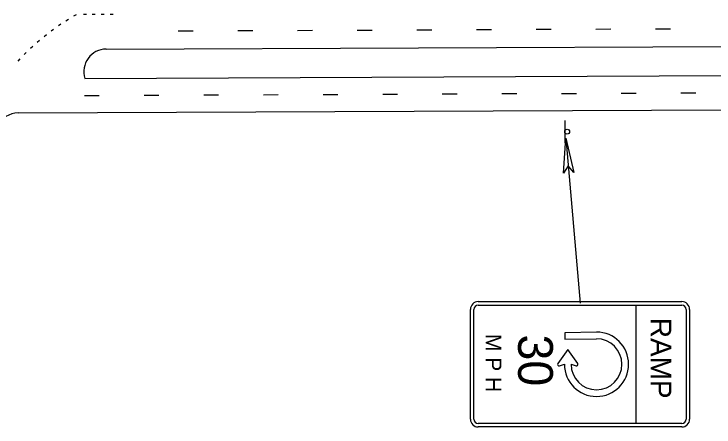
# Model space of a CAD drawing. Extents: x 582908 to 586039, y 1530940 to 1532988.
# Drawn here: x 583736 to 584469, y 1531974 to 1532406 of the extents above; entities that cross this region are included whole.
import ezdxf

# ---------------------------------------------------------------- set-up
doc = ezdxf.new("R2010")
doc.units = 0
for name, color, linetype in [('LeaderLine_dp', 7, 'Continuous'), ('PMStripe6W', 7, 'Continuous'), ('PMStripe6W(10-30)', 7, 'Continuous'), ('PMStripe6W(2-4)', 7, 'Continuous'), ('PMStripe6Y', 7, 'Continuous'), ('PMStripe6Y(2-4)', 7, 'Continuous'), ('PMStripe8W', 7, 'Continuous'), ('SignPanel', 7, 'Continuous'), ('SignSupport', 7, 'Continuous'), ('TextLabel', 7, 'Continuous')]:
    doc.layers.add(name, color=color, linetype=linetype)

msp = doc.modelspace()

# ---------------------------------------------------------------- linework, layer by layer
at = {"layer": 'LeaderLine_dp'}
for p, q in [((584311.27, 1532239.26), (584313.59, 1532276.18)), ((584313.59, 1532276.18), (584328.5, 1532103.42)), ((584313.59, 1532276.18), (584322.2, 1532240.21)), ((584316.11, 1532247.02), (584311.27, 1532239.26)), ((584322.2, 1532240.21), (584316.11, 1532247.02))]:
    msp.add_line(p, q, dxfattribs=at)
at = {"layer": 'PMStripe6W'}
msp.add_line((583739.97, 1532302.36), (584817.18, 1532307.14), dxfattribs=at)
at = {"layer": 'PMStripe6W(10-30)'}
for p, q in [((583907.67, 1532388.26), (583923.29, 1532388.33)), ((583970.17, 1532388.54), (583985.79, 1532388.61)), ((584032.66, 1532388.81), (584048.29, 1532388.88)), ((584095.16, 1532389.09), (584110.79, 1532389.16)), ((584157.66, 1532389.37), (584173.29, 1532389.44)), ((584220.16, 1532389.65), (584235.79, 1532389.72)), ((584282.66, 1532389.92), (584298.29, 1532389.99)), ((584345.16, 1532390.2), (584360.79, 1532390.27)), ((584407.66, 1532390.48), (584423.29, 1532390.55)), ((584184.26, 1532322.3), (584199.88, 1532322.37)), ((584246.75, 1532322.58), (584262.38, 1532322.64)), ((584309.25, 1532322.85), (584324.88, 1532322.92)), ((584371.75, 1532323.13), (584387.38, 1532323.2)), ((584434.25, 1532323.41), (584449.88, 1532323.48)), ((583809.26, 1532320.64), (583824.88, 1532320.71)), ((583871.76, 1532320.91), (583887.38, 1532320.98)), ((583934.26, 1532321.19), (583949.88, 1532321.26)), ((583996.76, 1532321.47), (584012.38, 1532321.54)), ((584059.26, 1532321.74), (584074.88, 1532321.81)), ((584121.76, 1532322.02), (584137.38, 1532322.09))]:
    msp.add_line(p, q, dxfattribs=at)
at = {"layer": 'PMStripe6W(2-4)'}
for p, q in [((583800.51, 1532405.07), (583797.81, 1532403.51)), ((583792.46, 1532400.27), (583789.81, 1532398.61)), ((583776.9, 1532389.81), (583774.39, 1532387.95)), ((583784.58, 1532395.18), (583782, 1532393.42)), ((583769.43, 1532384.16), (583766.98, 1532382.21)), ((583762.16, 1532378.23), (583759.78, 1532376.2)), ((583755.11, 1532372.05), (583752.82, 1532369.93)), ((583748.3, 1532365.61), (583746.08, 1532363.41)), ((583741.72, 1532358.93), (583739.59, 1532356.65))]:
    msp.add_line(p, q, dxfattribs=at)
at = {"layer": 'PMStripe6Y'}
msp.add_line((583809.79, 1532338.61), (584817.02, 1532343.07), dxfattribs=at)
at = {"layer": 'PMStripe6Y(2-4)'}
for p, q in [((583808.21, 1532405.79), (583811.33, 1532405.8)), ((583817.58, 1532405.83), (583820.71, 1532405.84)), ((583826.96, 1532405.87), (583830.08, 1532405.89)), ((583836.33, 1532405.91), (583839.46, 1532405.93))]:
    msp.add_line(p, q, dxfattribs=at)
at = {"layer": 'PMStripe8W'}
msp.add_line((583832.01, 1532369.18), (584975.98, 1532374.25), dxfattribs=at)
msp.add_arc((583832.11, 1532345.74), 23.44, 90.25398, 197.71158, dxfattribs=at)
at = {"layer": 'SignPanel'}
for p, q in [((584221.86, 1532105.03), (584435.14, 1532105.03)), ((584213.66, 1531981.98), (584213.66, 1532096.83)), ((584217.42, 1531981.98), (584217.42, 1532096.83)), ((584221.86, 1532101.27), (584435.14, 1532101.27)), ((584386.95, 1532101.27), (584386.95, 1531977.54)), ((584439.59, 1532096.83), (584439.59, 1531981.98)), ((584443.35, 1532096.83), (584443.35, 1531981.98)), ((584345.78, 1532073.07), (584312.62, 1532072.18)), ((584312.62, 1532072.18), (584312.62, 1532065.58)), ((584312.62, 1532065.58), (584345.78, 1532066.06)), ((584315.62, 1532055), (584305.14, 1532040.11)), ((584326.06, 1532040.08), (584315.62, 1532055)), ((584306.86, 1532037.77), (584312.12, 1532039.4)), ((584319.13, 1532039.4), (584324.34, 1532037.74)), ((584435.14, 1531977.54), (584221.86, 1531977.54)), ((584435.14, 1531973.78), (584221.86, 1531973.78))]:
    msp.add_line(p, q, dxfattribs=at)
for centre, radius, start, end in [((584221.86, 1532096.83), 8.2, 90, 180), ((584435.14, 1532096.83), 8.2, 360, 90), ((584221.86, 1532096.83), 4.44, 90, 180), ((584435.14, 1532096.83), 4.44, 360, 90), ((584345.78, 1532039.4), 33.67, 180, 89.99999), ((584345.78, 1532039.4), 26.65, 180, 89.99999), ((584306.39, 1532039.23), 1.53, 144.84325, 287.54399), ((584324.8, 1532039.2), 1.53, 252.29016, 34.99095), ((584221.86, 1531981.98), 8.2, 180, 270), ((584221.86, 1531981.98), 4.44, 180, 270), ((584435.14, 1531981.98), 8.2, 270, 360), ((584435.14, 1531981.98), 4.44, 270, 360)]:
    msp.add_arc(centre, radius, start, end, dxfattribs=at)
at = {"layer": 'SignSupport'}
msp.add_line((584312.58, 1532294.47), (584312.51, 1532271.19), dxfattribs=at)
msp.add_circle((584315.03, 1532282.82), 2.49, dxfattribs=at)
at = {"layer": 'TextLabel'}
msp.add_arc((583740.08, 1532277.36), 25, 90.25398, 153.19511, dxfattribs=at)

# ---------------------------------------------------------------- texts
at = {"layer": 'SignPanel'}
for s, height, p in [('RAMP', 21.885, (584402.4, 1532088.06)), ('M P H', 16.405, (584229.82, 1532071.12)), ('30', 36.421, (584263.66, 1532070.59))]:
    msp.add_text(s, height=height, rotation=270, dxfattribs=at).set_placement(p)

doc.saveas('drawing.dxf')
